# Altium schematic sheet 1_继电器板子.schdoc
size 309 x 223 mm; Symbol: Sheet-Symbol_A4; Device: Sheet-Symbol_A4; Company: 嘉立创EDA; Version: V1.0; Page Size: A4; @Project Name: New Project_2025-01-23_00-40-50; @Page Count: 4; @Update Date: 2025-08-15; @Create Date: 2025-07-30; @Schematic Name: Schematic3_7; @Page No: 1; @Page Name: 继电器板子; @Board Name: cm4; @Create Time: 15:34:35; @Update Time: 00:10:44
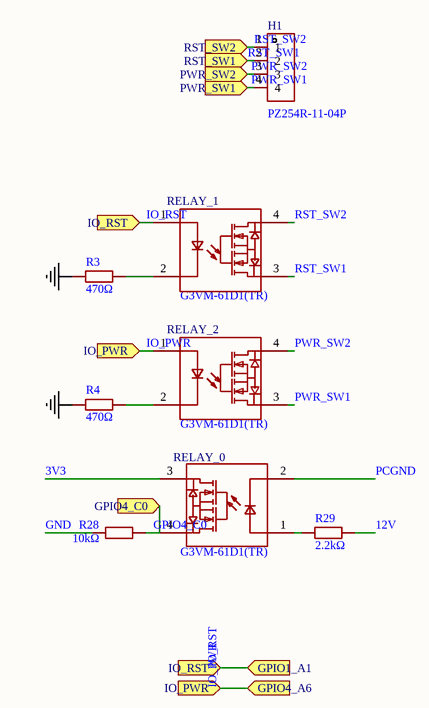
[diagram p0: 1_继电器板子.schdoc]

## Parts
H1  PZ254R-11-04P  [HDR-TH_4P-P2.54-H-M-W10.4]
R3  470Ω  [R0603]
R4  470Ω  [R0603]
R28  10kΩ  [R0603]
R29  2.2kΩ  [R0603]
RELAY_0  G3VM-61D1(TR)  [SMD-4_L4.6-W6.4-P2.54-LS10.0-BL]
RELAY_1  G3VM-61D1(TR)  [SMD-4_L4.6-W6.4-P2.54-LS10.0-BL]
RELAY_2  G3VM-61D1(TR)  [SMD-4_L4.6-W6.4-P2.54-LS10.0-BL]

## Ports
GPIO1_A1 (in), GPIO4_A6 (in), GPIO4_C0 (in), IO_PWR (in), IO_RST (in), PWR_SW1 (in), PWR_SW2 (in), RST_SW1 (in), RST_SW2 (in)

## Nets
GND: R3.1 R4.1 R28.1
3V3: RELAY_0.3
12V: R29.2
GPIO4_C0: R28.2 RELAY_0.4 ; port GPIO4_C0
IO_PWR: RELAY_2.1 ; port IO_PWR, port GPIO4_A6
IO_RST: RELAY_1.1 ; port IO_RST, port GPIO1_A1
PCGND: RELAY_0.2
PWR_SW1: H1.4 RELAY_2.3 ; port PWR_SW1
PWR_SW2: H1.3 RELAY_2.4 ; port PWR_SW2
RST_SW1: H1.2 RELAY_1.3 ; port RST_SW1
RST_SW2: H1.1 RELAY_1.4 ; port RST_SW2
NetR3_2: R3.2 RELAY_1.2
NetR4_2: R4.2 RELAY_2.2
NetR29_1: R29.1 RELAY_0.1

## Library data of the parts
H1 = PZ254R-11-04P: Manufacturer: XFCN(兴飞); Add into BOM: yes; Pin Structure: 1x4P; Pitch: 2.54mm; Circluar Pins/Square Pins: 方针
R3 R4 = 0603WAF4700T5E: Manufacturer: UNI-ROYAL(厚声); Symbol: 电阻; Add into BOM: yes; Tolerance: ±1%; Power(Watts): 100mW; Overload Voltage (Max): 75V; Temperature Coefficient: ±100ppm/℃
R28 = 0603WAF1002T5E: Manufacturer: UNI-ROYAL(厚声); Symbol: 电阻; Add into BOM: yes; Tolerance: ±1%; Power(Watts): 100mW; Voltage-Supply(Max): 75V; Temperature Coefficient: ±100ppm/℃
R29 = 0603WAF2201T5E: Manufacturer: UNI-ROYAL(厚声); Symbol: 电阻; Add into BOM: yes; Tolerance: ±1%; Power(Watts): 100mW; Overload Voltage (Max): 75V; Temperature Coefficient: ±100ppm/℃
RELAY_0-RELAY_2 = G3VM-61D1(TR): Manufacturer: OMRON(欧姆龙); Add into BOM: yes; Relay Contact Form: 1 Form A(SPST-NO); Load Type: AC,DC; Input Forward Voltage: 1.15V; Voltage - Load: 60V; Continuous Load Current: 500mA; On Resistance: 1Ω; Isolation Voltage(rms): 2.5kV; Turn-on time: 800us; Turn-off time: 100us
